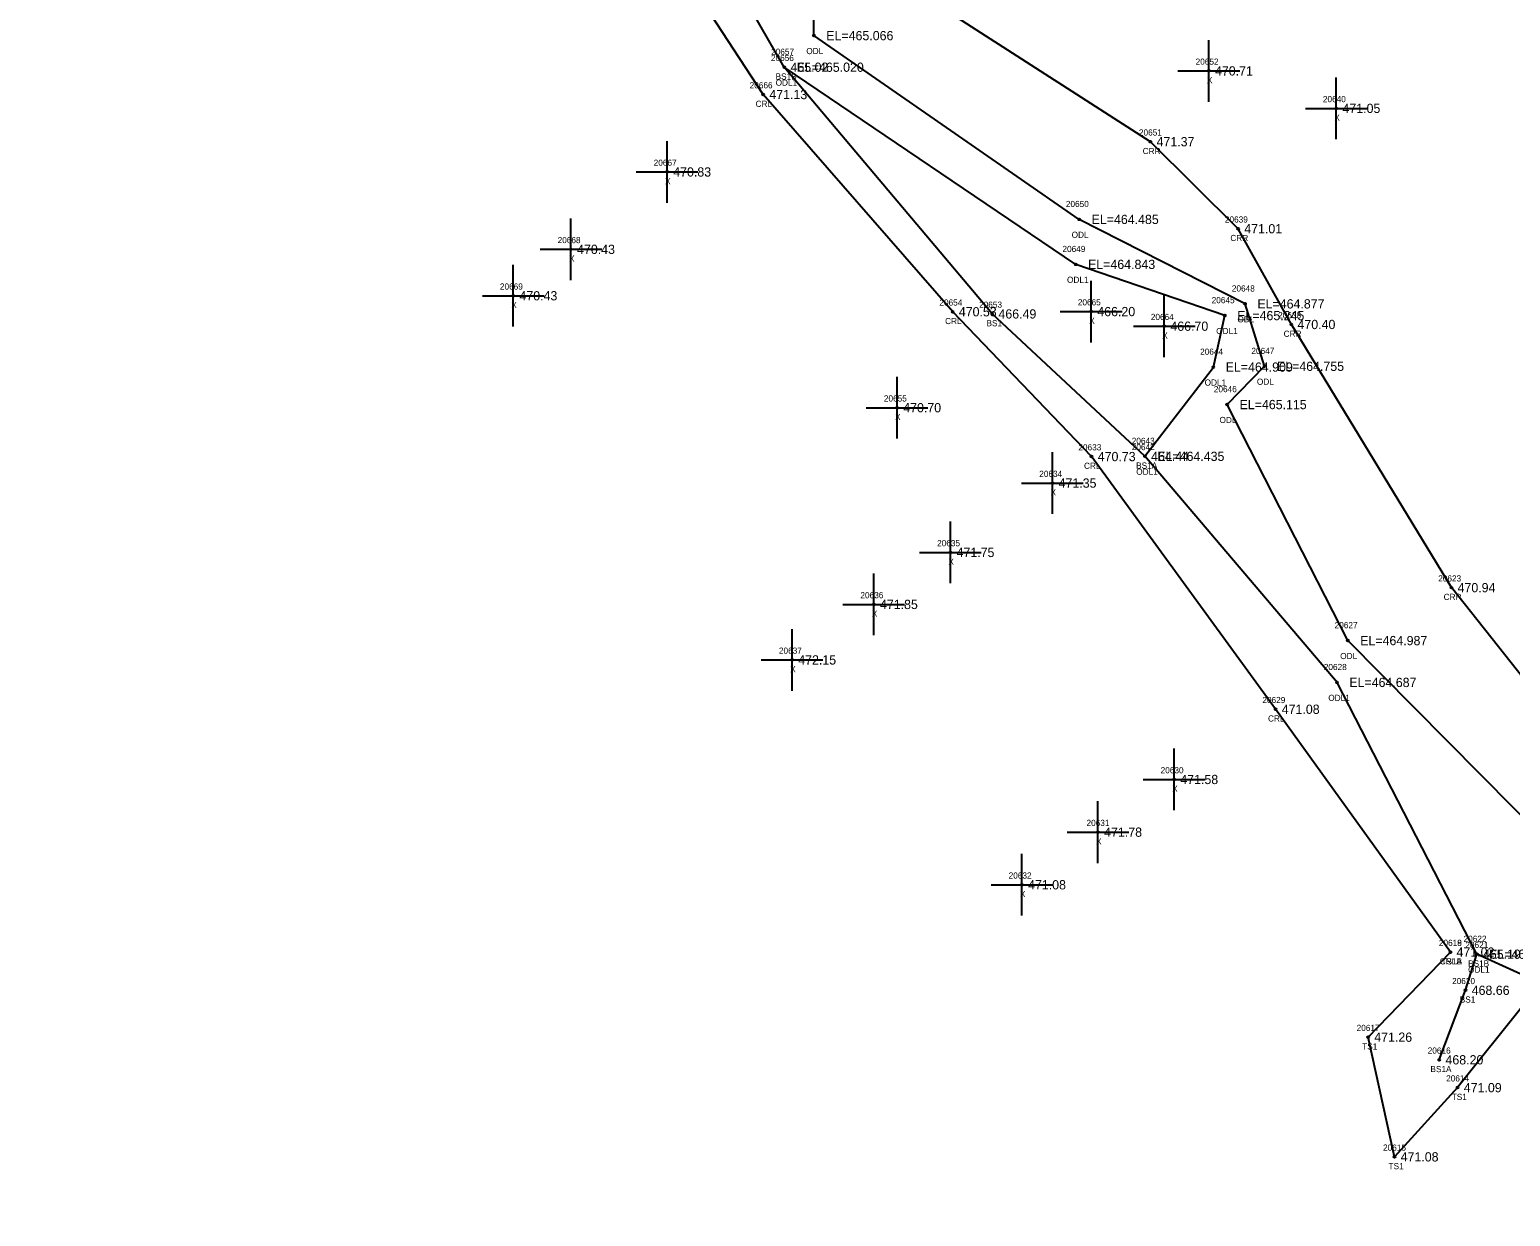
# Model space of a CAD drawing. Extents: x 1741010 to 1742139, y 749382 to 750625.
# Drawn here: x 1741616.4 to 1741856.4, y 749694.1 to 749886.5 of the extents above; entities that cross this region are included whole.
import ezdxf

# ---------------------------------------------------------------- set-up
doc = ezdxf.new("R2010")
doc.units = 0
for name, color, linetype in [('RD_DTM_BkLn2', 7, 'Continuous'), ('RD_DTM_BkLn_txCode', 7, 'Continuous'), ('RD_EX_H2O', 7, 'Continuous'), ('RD_EX_H2O_txCode', 7, 'Continuous'), ('RD_EX_Misc', 7, 'Continuous'), ('RD_EX_Misc_txCode', 7, 'Continuous'), ('RD_EX_TX_H2O_ELEV', 7, 'Continuous'), ('RD_EX_TX_Misc_ELEV', 7, 'Continuous'), ('RD_SMD_Locator', 7, 'Continuous')]:
    doc.layers.add(name, color=color, linetype=linetype)

msp = doc.modelspace()

# ---------------------------------------------------------------- linework, layer by layer
at = {"layer": 'RD_DTM_BkLn2'}
for points in [[(1741797.14, 749817.35), (1741772.4, 749840.43), (1741738.7, 749880.42)], [(1741858.65, 749728.58), (1741847.81, 749715.02), (1741837.58, 749703.8), (1741833.3, 749723.2), (1741846.63, 749736.99)], [(1741844.84, 749719.53), (1741849.09, 749730.8), (1741850.91, 749736.65)]]:
    msp.add_lwpolyline(points, dxfattribs=at)
at = {"layer": 'RD_EX_H2O'}
for points in [[(1742009.73, 749699.92), (1741998.41, 749723.73), (1741963.19, 749743.52), (1741899.78, 749744.87), (1741875.61, 749759.72), (1741846.8, 749796.06), (1741820.86, 749838.72), (1741812.23, 749854.24), (1741798.02, 749868.34), (1741757.86, 749894.19), (1741733.12, 749942.57), (1741724.29, 749959.1), (1741692.79, 749978.15), (1741670.02, 749986.94), (1741660.12, 749986.72), (1741653.47, 749993.98), (1741643.26, 750008.63), (1741623.07, 750045.53)], [(1741979.95, 749694.15), (1741975.81, 749711.2), (1741958.44, 749721.88), (1741894.61, 749726.87), (1741877.76, 749724.44), (1741850.91, 749736.65), (1741828.26, 749780.7), (1741797.14, 749817.35), (1741808.22, 749831.81), (1741810.09, 749840.16), (1741785.92, 749848.46), (1741738.7, 749880.42), (1741729.53, 749896.38), (1741713.46, 749926.44), (1741709.24, 749941.41), (1741681.29, 749963.78), (1741670.93, 749974.67), (1741649.76, 749966.83), (1741639.61, 749974.72), (1741630.05, 749994.96), (1741605.22, 750035.39), (1741604.28, 750042.48)], [(1741997.88, 749696.99), (1741991.24, 749718.21), (1741959.63, 749735.24), (1741894.45, 749731.15), (1741878.5, 749730.08), (1741867.7, 749749.38), (1741830.02, 749787.48), (1741810.47, 749825.74), (1741816.53, 749831.94), (1741813.36, 749842.06), (1741786.5, 749855.75), (1741743.5, 749885.54), (1741743.36, 749896.22), (1741733.61, 749897.85), (1741720.42, 749929.78), (1741722.99, 749946.15), (1741719.27, 749955.78), (1741689.88, 749975.02), (1741668.65, 749983.88), (1741656.91, 749978.01), (1741649.96, 749989.33), (1741640.41, 750007.7), (1741621.8, 750037.62), (1741614.56, 750040.31)], [(1741846.63, 749736.99), (1741818.31, 749776.35), (1741788.49, 749817.31), (1741765.98, 749840.78), (1741735.27, 749875.99), (1741723.94, 749893.4), (1741708.1, 749924.67), (1741701.67, 749936.46), (1741685.41, 749952.28)]]:
    msp.add_lwpolyline(points, dxfattribs=at)
at = {"layer": 'RD_EX_Misc'}
for p, q in [((1741807.49, 749874.82), (1741807.49, 749884.82)), ((1741802.49, 749879.82), (1741812.49, 749879.82)), ((1741828.15, 749868.75), (1741828.15, 749878.75)), ((1741823.15, 749873.75), (1741833.15, 749873.75)), ((1741719.7, 749858.44), (1741719.7, 749868.44)), ((1741714.7, 749863.44), (1741724.7, 749863.44)), ((1741704.12, 749845.9), (1741704.12, 749855.9)), ((1741699.12, 749850.9), (1741709.12, 749850.9)), ((1741694.78, 749838.37), (1741694.78, 749848.37)), ((1741788.42, 749835.81), (1741788.42, 749845.81)), ((1741689.78, 749843.37), (1741699.78, 749843.37)), ((1741800.26, 749833.44), (1741800.26, 749843.44)), ((1741783.42, 749840.81), (1741793.42, 749840.81)), ((1741795.26, 749838.44), (1741805.26, 749838.44)), ((1741756.97, 749820.23), (1741756.97, 749830.23)), ((1741751.97, 749825.23), (1741761.97, 749825.23)), ((1741782.15, 749808.01), (1741782.15, 749818.01)), ((1741777.15, 749813.01), (1741787.15, 749813.01)), ((1741765.61, 749796.77), (1741765.61, 749806.77)), ((1741760.61, 749801.77), (1741770.61, 749801.77)), ((1741753.2, 749788.34), (1741753.2, 749798.34)), ((1741748.2, 749793.34), (1741758.2, 749793.34)), ((1741739.96, 749779.35), (1741739.96, 749789.35)), ((1741734.96, 749784.35), (1741744.96, 749784.35)), ((1741801.87, 749759.97), (1741801.87, 749769.97)), ((1741796.87, 749764.97), (1741806.87, 749764.97)), ((1741789.53, 749751.43), (1741789.53, 749761.43)), ((1741784.53, 749756.43), (1741794.53, 749756.43)), ((1741777.2, 749742.9), (1741777.2, 749752.9)), ((1741772.2, 749747.9), (1741782.2, 749747.9))]:
    msp.add_line(p, q, dxfattribs=at)
at = {"layer": 'RD_SMD_Locator'}
for centre in [(1741743.5, 749885.54), (1741738.7, 749880.42), (1741738.7, 749880.42), (1741807.49, 749879.82), (1741735.27, 749875.99), (1741828.15, 749873.75), (1741798.02, 749868.34), (1741719.7, 749863.44), (1741786.5, 749855.75), (1741812.23, 749854.24), (1741704.12, 749850.9), (1741785.92, 749848.46), (1741694.78, 749843.37), (1741813.36, 749842.06), (1741765.98, 749840.78), (1741772.4, 749840.43), (1741788.42, 749840.81), (1741810.09, 749840.16), (1741800.26, 749838.44), (1741820.86, 749838.72), (1741808.22, 749831.81), (1741816.53, 749831.94), (1741756.97, 749825.23), (1741810.47, 749825.74), (1741788.49, 749817.31), (1741797.14, 749817.35), (1741797.14, 749817.35), (1741782.15, 749813.01), (1741765.61, 749801.77), (1741846.8, 749796.06), (1741753.2, 749793.34), (1741830.02, 749787.48), (1741739.96, 749784.35), (1741828.26, 749780.7), (1741818.31, 749776.35), (1741801.87, 749764.97), (1741789.53, 749756.43), (1741777.2, 749747.9), (1741846.63, 749736.99), (1741846.63, 749736.99), (1741850.91, 749736.65), (1741850.91, 749736.65), (1741849.09, 749730.8), (1741833.3, 749723.2), (1741844.84, 749719.53), (1741847.81, 749715.02), (1741837.58, 749703.8)]:
    msp.add_circle(centre, 0.15, dxfattribs=at)

# ---------------------------------------------------------------- texts
at = {"layer": 'RD_DTM_BkLn_txCode'}
for s, p in [('20656', (1741736.53, 749881.42)), ('BS1B', (1741737.28, 749878.42)), ('20653', (1741770.26, 749841.43)), ('BS1', (1741771.46, 749838.43)), ('20642', (1741795, 749818.35)), ('BS1A', (1741795.71, 749815.35)), ('20618', (1741844.77, 749737.99)), ('20621', (1741849.06, 749737.65)), ('TS1B', (1741845.19, 749734.99)), ('BS1B', (1741849.5, 749734.65)), ('20620', (1741846.91, 749731.8)), ('BS1', (1741848.15, 749728.8)), ('20617', (1741831.44, 749724.2)), ('TS1', (1741832.34, 749721.2)), ('20616', (1741842.96, 749720.53)), ('BS1A', (1741843.4, 749717.53)), ('20614', (1741845.95, 749716.02)), ('TS1', (1741846.85, 749713.02)), ('20615', (1741835.72, 749704.8)), ('TS1', (1741836.62, 749701.8))]:
    msp.add_text(s, height=1, dxfattribs=at).set_placement(p)
at = {"layer": 'RD_EX_H2O_txCode'}
for s, p in [('20657', (1741736.56, 749882.42)), ('ODL', (1741742.26, 749882.54)), ('ODL1', (1741737.29, 749877.42)), ('20666', (1741733.08, 749876.99)), ('CRL', (1741734.04, 749873.99)), ('20651', (1741796.16, 749869.34)), ('CRR', (1741796.77, 749866.34)), ('20650', (1741784.32, 749857.75)), ('20639', (1741810.09, 749855.24)), ('ODL', (1741785.26, 749852.75)), ('CRR', (1741810.98, 749852.24)), ('20649', (1741783.77, 749850.46)), ('ODL1', (1741784.51, 749845.46)), ('20648', (1741811.22, 749844.06)), ('20654', (1741763.83, 749841.78)), ('20645', (1741807.95, 749842.16)), ('CRL', (1741764.75, 749838.78)), ('ODL', (1741812.12, 749839.06)), ('20638', (1741818.72, 749839.72)), ('ODL1', (1741808.68, 749837.16)), ('CRR', (1741819.61, 749836.72)), ('20647', (1741814.39, 749833.94)), ('20644', (1741806.08, 749833.81)), ('ODL1', (1741806.81, 749828.81)), ('20646', (1741808.3, 749827.74)), ('ODL', (1741815.28, 749828.94)), ('ODL', (1741809.22, 749822.74)), ('20633', (1741786.35, 749818.31)), ('20643', (1741795, 749819.35)), ('CRL', (1741787.26, 749815.31)), ('ODL1', (1741795.73, 749814.35)), ('20623', (1741844.66, 749797.06)), ('CRR', (1741845.54, 749794.06)), ('20627', (1741827.88, 749789.48)), ('ODL', (1741828.78, 749784.48)), ('20628', (1741826.12, 749782.7)), ('20629', (1741816.17, 749777.35)), ('ODL1', (1741826.85, 749777.7)), ('CRL', (1741817.08, 749774.35)), ('20619', (1741844.77, 749737.99)), ('20622', (1741848.77, 749738.65)), ('CRLA', (1741844.91, 749734.99)), ('ODL1', (1741849.5, 749733.65))]:
    msp.add_text(s, height=1, dxfattribs=at).set_placement(p)
at = {"layer": 'RD_EX_Misc_txCode'}
for s, p in [('20652', (1741805.35, 749880.82)), ('X', (1741807.18, 749877.82)), ('20640', (1741825.97, 749874.75)), ('X', (1741827.83, 749871.75)), ('20667', (1741717.53, 749864.44)), ('X', (1741719.38, 749861.44)), ('20668', (1741701.96, 749851.9)), ('X', (1741703.81, 749848.9)), ('20669', (1741692.61, 749844.37)), ('X', (1741694.46, 749841.37)), ('20665', (1741786.26, 749841.81)), ('X', (1741788.11, 749838.81)), ('20664', (1741798.09, 749839.44)), ('X', (1741799.94, 749836.44)), ('20655', (1741754.83, 749826.23)), ('X', (1741756.65, 749823.23)), ('20634', (1741780.01, 749814.01)), ('X', (1741781.84, 749811.01)), ('20635', (1741763.46, 749802.77)), ('X', (1741765.29, 749799.77)), ('20636', (1741751.03, 749794.34)), ('X', (1741752.88, 749791.34)), ('20637', (1741737.82, 749785.35)), ('X', (1741739.65, 749782.35)), ('20630', (1741799.68, 749765.97)), ('X', (1741801.55, 749762.97)), ('20631', (1741787.67, 749757.43)), ('X', (1741789.22, 749754.43)), ('20632', (1741775.05, 749748.9)), ('X', (1741776.88, 749745.9))]:
    msp.add_text(s, height=1, dxfattribs=at).set_placement(p)
at = {"layer": 'RD_EX_TX_H2O_ELEV'}
for s, p in [('EL=465.066', (1741745.5, 749884.79)), ('EL=465.020', (1741740.7, 749879.67)), ('471.13', (1741736.27, 749875.24)), ('471.37', (1741799.02, 749867.59)), ('EL=464.485', (1741788.5, 749855)), ('471.01', (1741813.23, 749853.49)), ('EL=464.843', (1741787.92, 749847.71)), ('EL=464.877', (1741815.36, 749841.31)), ('470.53', (1741766.98, 749840.03)), ('EL=465.245', (1741812.09, 749839.41)), ('470.40', (1741821.86, 749837.97)), ('EL=464.909', (1741810.22, 749831.06)), ('EL=464.755', (1741818.53, 749831.19)), ('EL=465.115', (1741812.47, 749824.99)), ('470.73', (1741789.49, 749816.56)), ('EL=464.435', (1741799.14, 749816.6)), ('470.94', (1741847.8, 749795.31)), ('EL=464.987', (1741832.02, 749786.73)), ('EL=464.687', (1741830.26, 749779.95)), ('471.08', (1741819.31, 749775.6)), ('471.02', (1741847.63, 749736.24)), ('EL=465.186', (1741852.91, 749735.9))]:
    msp.add_text(s, height=1.5, dxfattribs=at).set_placement(p)
at = {"layer": 'RD_EX_TX_Misc_ELEV'}
for s, p in [('465.02', (1741739.7, 749879.67)), ('470.71', (1741808.49, 749879.07)), ('471.05', (1741829.15, 749873)), ('470.83', (1741720.7, 749862.69)), ('470.43', (1741705.12, 749850.15)), ('470.43', (1741695.78, 749842.62)), ('466.49', (1741773.4, 749839.68)), ('466.20', (1741789.42, 749840.06)), ('466.70', (1741801.26, 749837.69)), ('470.70', (1741757.97, 749824.48)), ('464.44', (1741798.14, 749816.6)), ('471.35', (1741783.15, 749812.26)), ('471.75', (1741766.61, 749801.02)), ('471.85', (1741754.2, 749792.59)), ('472.15', (1741740.96, 749783.6)), ('471.58', (1741802.87, 749764.22)), ('471.78', (1741790.53, 749755.68)), ('471.08', (1741778.2, 749747.15)), ('471.02', (1741847.63, 749736.24)), ('465.19', (1741851.91, 749735.9)), ('468.66', (1741850.09, 749730.05)), ('471.26', (1741834.3, 749722.45)), ('468.20', (1741845.84, 749718.78)), ('471.09', (1741848.81, 749714.27)), ('471.08', (1741838.58, 749703.05))]:
    msp.add_text(s, height=1.5, dxfattribs=at).set_placement(p)

doc.saveas('drawing.dxf')
